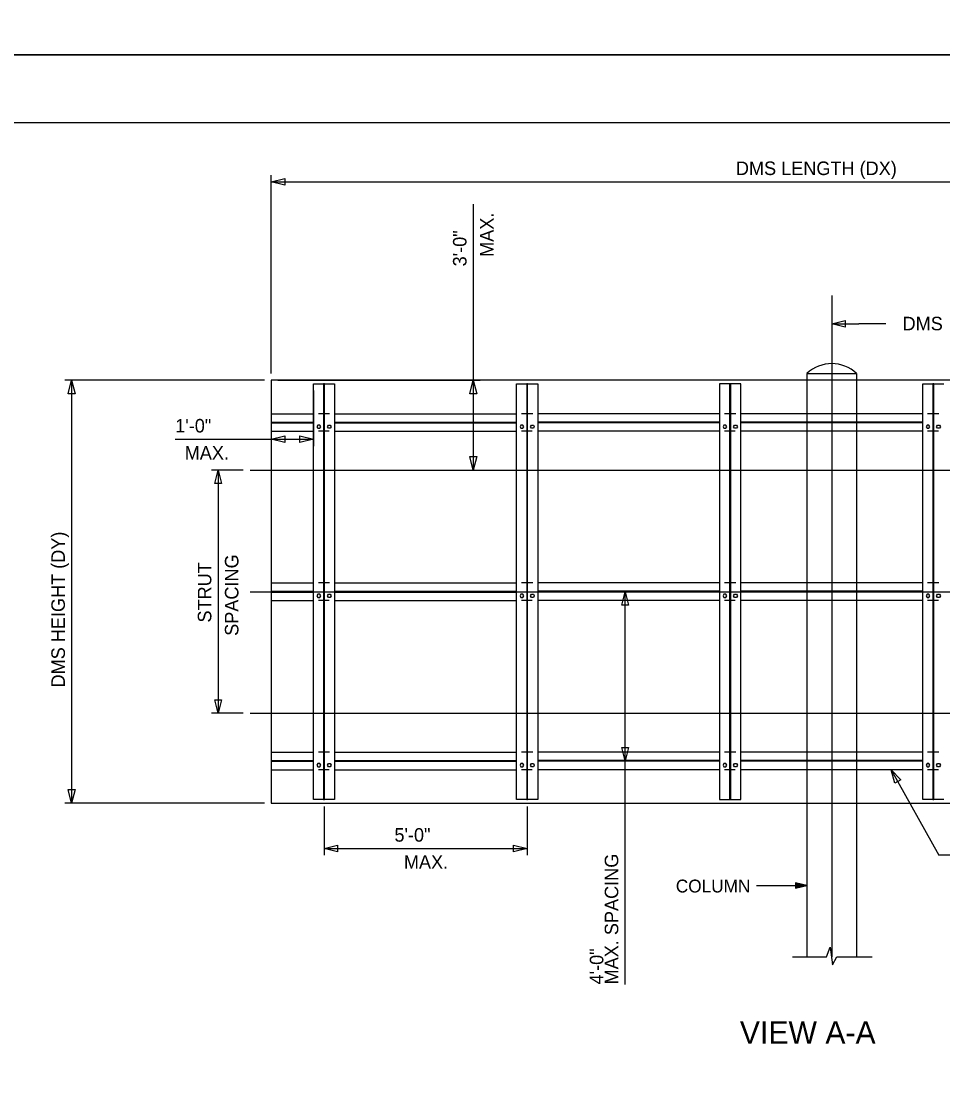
# Model space of a CAD drawing. Extents: x 3829340 to 3831660, y 499389 to 501171.
# Drawn here: x 3830412.4 to 3830616.6, y 499757.1 to 499990.7 of the extents above; entities that cross this region are included whole.
import ezdxf

# ---------------------------------------------------------------- set-up
doc = ezdxf.new("R2010")
doc.units = 0
for name, color, linetype in [('0-ANCHOR', 7, 'Continuous'), ('10', 7, 'Continuous'), ('2', 7, 'Continuous'), ('20', 7, 'Continuous'), ('CNTR', 7, 'Continuous'), ('Default', 7, 'Continuous'), ('DIM TXT', 7, 'Continuous'), ('PLT-BNDY', 7, 'Continuous'), ('sign', 7, 'Continuous'), ('structure', 7, 'Continuous')]:
    doc.layers.add(name, color=color, linetype=linetype)

msp = doc.modelspace()

# ---------------------------------------------------------------- linework, layer by layer
at = {"layer": '0-ANCHOR'}
for p, q in [((3830478.12, 499901.15), (3830477.91, 499900.79)), ((3830477.91, 499900.79), (3830478.12, 499900.43)), ((3830478.53, 499901.15), (3830478.12, 499901.15)), ((3830478.74, 499900.79), (3830478.53, 499901.15)), ((3830478.53, 499900.43), (3830478.74, 499900.79)), ((3830480.24, 499900.79), (3830480.45, 499901.15)), ((3830480.45, 499900.43), (3830480.24, 499900.79)), ((3830480.45, 499901.15), (3830480.87, 499901.15)), ((3830480.87, 499901.15), (3830481.07, 499900.79)), ((3830481.07, 499900.79), (3830480.87, 499900.43)), ((3830523.12, 499901.15), (3830522.91, 499900.79)), ((3830522.91, 499900.79), (3830523.12, 499900.43)), ((3830523.53, 499901.15), (3830523.12, 499901.15)), ((3830523.74, 499900.79), (3830523.53, 499901.15)), ((3830523.53, 499900.43), (3830523.74, 499900.79)), ((3830525.24, 499900.79), (3830525.45, 499901.15)), ((3830525.45, 499900.43), (3830525.24, 499900.79)), ((3830525.45, 499901.15), (3830525.87, 499901.15)), ((3830525.87, 499901.15), (3830526.07, 499900.79)), ((3830526.07, 499900.79), (3830525.87, 499900.43)), ((3830568.11, 499901.15), (3830567.91, 499900.79)), ((3830567.91, 499900.79), (3830568.11, 499900.43)), ((3830568.53, 499901.15), (3830568.11, 499901.15)), ((3830568.74, 499900.79), (3830568.53, 499901.15)), ((3830568.53, 499900.43), (3830568.74, 499900.79)), ((3830570.24, 499900.79), (3830570.45, 499901.15)), ((3830570.45, 499900.43), (3830570.24, 499900.79)), ((3830570.45, 499901.15), (3830570.86, 499901.15)), ((3830570.86, 499901.15), (3830571.07, 499900.79)), ((3830571.07, 499900.79), (3830570.86, 499900.43)), ((3830613.11, 499901.15), (3830612.91, 499900.79)), ((3830612.91, 499900.79), (3830613.11, 499900.43)), ((3830613.53, 499901.15), (3830613.11, 499901.15)), ((3830613.74, 499900.79), (3830613.53, 499901.15)), ((3830613.53, 499900.43), (3830613.74, 499900.79)), ((3830615.24, 499900.79), (3830615.45, 499901.15)), ((3830615.45, 499900.43), (3830615.24, 499900.79)), ((3830615.45, 499901.15), (3830615.86, 499901.15)), ((3830615.86, 499901.15), (3830616.07, 499900.79)), ((3830616.07, 499900.79), (3830615.86, 499900.43)), ((3830478.12, 499900.43), (3830478.53, 499900.43)), ((3830480.87, 499900.43), (3830480.45, 499900.43)), ((3830523.12, 499900.43), (3830523.53, 499900.43)), ((3830525.87, 499900.43), (3830525.45, 499900.43)), ((3830568.11, 499900.43), (3830568.53, 499900.43)), ((3830570.86, 499900.43), (3830570.45, 499900.43)), ((3830613.11, 499900.43), (3830613.53, 499900.43)), ((3830615.86, 499900.43), (3830615.45, 499900.43)), ((3830478.12, 499863.65), (3830477.91, 499863.29)), ((3830478.53, 499863.65), (3830478.12, 499863.65)), ((3830478.74, 499863.29), (3830478.53, 499863.65)), ((3830480.24, 499863.29), (3830480.45, 499863.65)), ((3830480.45, 499863.65), (3830480.87, 499863.65)), ((3830480.87, 499863.65), (3830481.07, 499863.29)), ((3830523.12, 499863.65), (3830522.91, 499863.29)), ((3830523.53, 499863.65), (3830523.12, 499863.65)), ((3830523.74, 499863.29), (3830523.53, 499863.65)), ((3830525.24, 499863.29), (3830525.45, 499863.65)), ((3830525.45, 499863.65), (3830525.87, 499863.65)), ((3830525.87, 499863.65), (3830526.07, 499863.29)), ((3830568.11, 499863.65), (3830567.91, 499863.29)), ((3830568.53, 499863.65), (3830568.11, 499863.65)), ((3830568.74, 499863.29), (3830568.53, 499863.65)), ((3830570.24, 499863.29), (3830570.45, 499863.65)), ((3830570.45, 499863.65), (3830570.86, 499863.65)), ((3830570.86, 499863.65), (3830571.07, 499863.29)), ((3830613.11, 499863.65), (3830612.91, 499863.29)), ((3830613.53, 499863.65), (3830613.11, 499863.65)), ((3830613.74, 499863.29), (3830613.53, 499863.65)), ((3830615.24, 499863.29), (3830615.45, 499863.65)), ((3830615.45, 499863.65), (3830615.86, 499863.65)), ((3830615.86, 499863.65), (3830616.07, 499863.29)), ((3830477.91, 499863.29), (3830478.12, 499862.93)), ((3830478.12, 499862.93), (3830478.53, 499862.93)), ((3830478.53, 499862.93), (3830478.74, 499863.29)), ((3830480.45, 499862.93), (3830480.24, 499863.29)), ((3830480.87, 499862.93), (3830480.45, 499862.93)), ((3830481.07, 499863.29), (3830480.87, 499862.93)), ((3830522.91, 499863.29), (3830523.12, 499862.93)), ((3830523.12, 499862.93), (3830523.53, 499862.93)), ((3830523.53, 499862.93), (3830523.74, 499863.29)), ((3830525.45, 499862.93), (3830525.24, 499863.29)), ((3830525.87, 499862.93), (3830525.45, 499862.93)), ((3830526.07, 499863.29), (3830525.87, 499862.93)), ((3830567.91, 499863.29), (3830568.11, 499862.93)), ((3830568.11, 499862.93), (3830568.53, 499862.93)), ((3830568.53, 499862.93), (3830568.74, 499863.29)), ((3830570.45, 499862.93), (3830570.24, 499863.29)), ((3830570.86, 499862.93), (3830570.45, 499862.93)), ((3830571.07, 499863.29), (3830570.86, 499862.93)), ((3830612.91, 499863.29), (3830613.11, 499862.93)), ((3830613.11, 499862.93), (3830613.53, 499862.93)), ((3830613.53, 499862.93), (3830613.74, 499863.29)), ((3830615.45, 499862.93), (3830615.24, 499863.29)), ((3830615.86, 499862.93), (3830615.45, 499862.93)), ((3830616.07, 499863.29), (3830615.86, 499862.93)), ((3830478.12, 499826.15), (3830477.91, 499825.79)), ((3830478.53, 499826.15), (3830478.12, 499826.15)), ((3830478.74, 499825.79), (3830478.53, 499826.15)), ((3830480.24, 499825.79), (3830480.45, 499826.15)), ((3830480.45, 499826.15), (3830480.87, 499826.15)), ((3830480.87, 499826.15), (3830481.07, 499825.79)), ((3830523.12, 499826.15), (3830522.91, 499825.79)), ((3830523.53, 499826.15), (3830523.12, 499826.15)), ((3830523.74, 499825.79), (3830523.53, 499826.15)), ((3830525.24, 499825.79), (3830525.45, 499826.15)), ((3830525.45, 499826.15), (3830525.87, 499826.15)), ((3830525.87, 499826.15), (3830526.07, 499825.79)), ((3830568.11, 499826.15), (3830567.91, 499825.79)), ((3830568.53, 499826.15), (3830568.11, 499826.15)), ((3830568.74, 499825.79), (3830568.53, 499826.15)), ((3830570.24, 499825.79), (3830570.45, 499826.15)), ((3830570.45, 499826.15), (3830570.86, 499826.15)), ((3830570.86, 499826.15), (3830571.07, 499825.79)), ((3830613.11, 499826.15), (3830612.91, 499825.79)), ((3830613.53, 499826.15), (3830613.11, 499826.15)), ((3830613.74, 499825.79), (3830613.53, 499826.15)), ((3830615.24, 499825.79), (3830615.45, 499826.15)), ((3830615.45, 499826.15), (3830615.86, 499826.15)), ((3830615.86, 499826.15), (3830616.07, 499825.79)), ((3830477.91, 499825.79), (3830478.12, 499825.43)), ((3830478.12, 499825.43), (3830478.53, 499825.43)), ((3830478.53, 499825.43), (3830478.74, 499825.79)), ((3830480.45, 499825.43), (3830480.24, 499825.79)), ((3830480.87, 499825.43), (3830480.45, 499825.43)), ((3830481.07, 499825.79), (3830480.87, 499825.43)), ((3830522.91, 499825.79), (3830523.12, 499825.43)), ((3830523.12, 499825.43), (3830523.53, 499825.43)), ((3830523.53, 499825.43), (3830523.74, 499825.79)), ((3830525.45, 499825.43), (3830525.24, 499825.79)), ((3830525.87, 499825.43), (3830525.45, 499825.43)), ((3830526.07, 499825.79), (3830525.87, 499825.43)), ((3830567.91, 499825.79), (3830568.11, 499825.43)), ((3830568.11, 499825.43), (3830568.53, 499825.43)), ((3830568.53, 499825.43), (3830568.74, 499825.79)), ((3830570.45, 499825.43), (3830570.24, 499825.79)), ((3830570.86, 499825.43), (3830570.45, 499825.43)), ((3830571.07, 499825.79), (3830570.86, 499825.43)), ((3830612.91, 499825.79), (3830613.11, 499825.43)), ((3830613.11, 499825.43), (3830613.53, 499825.43)), ((3830613.53, 499825.43), (3830613.74, 499825.79)), ((3830615.45, 499825.43), (3830615.24, 499825.79)), ((3830615.86, 499825.43), (3830615.45, 499825.43)), ((3830616.07, 499825.79), (3830615.86, 499825.43))]:
    msp.add_line(p, q, dxfattribs=at)
at = {"layer": '10'}
for p, q in [((3830575.31, 499799.1), (3830586.47, 499799.1)), ((3830586.47, 499799.1), (3830583.98, 499799.72)), ((3830583.98, 499799.72), (3830583.98, 499798.48)), ((3830583.98, 499798.48), (3830586.47, 499799.1)), ((3830585.86, 499799.1), (3830584.13, 499799.53)), ((3830584.13, 499799.53), (3830584.13, 499798.66)), ((3830584.13, 499798.66), (3830585.86, 499799.1)), ((3830585.25, 499799.1), (3830584.27, 499799.34)), ((3830584.27, 499799.34), (3830584.27, 499798.85)), ((3830584.27, 499798.85), (3830585.25, 499799.1)), ((3830584.33, 499799.02), (3830584.65, 499799.1)), ((3830584.65, 499799.1), (3830584.35, 499799.17))]:
    msp.add_line(p, q, dxfattribs=at)
at = {"layer": '2'}
msp.add_line((3830220.96, 499968.19), (3831006.96, 499968.19), dxfattribs=at)
at = {"layer": '20'}
for p, q in [((3830586.47, 499912.57), (3830597.51, 499912.57)), ((3830586.47, 499912.57), (3830586.47, 499911.09)), ((3830597.51, 499912.57), (3830597.51, 499911.09)), ((3830586.47, 499911.09), (3830586.47, 499817.35)), ((3830597.51, 499911.09), (3830597.51, 499817.35)), ((3830586.47, 499817.35), (3830586.47, 499783.31)), ((3830597.51, 499817.35), (3830597.51, 499783.31)), ((3830590.81, 499783.31), (3830591.64, 499785.42)), ((3830591.64, 499785.42), (3830592.18, 499781.54)), ((3830583.27, 499783.31), (3830590.81, 499783.31)), ((3830592.18, 499781.54), (3830593.12, 499783.31)), ((3830593.12, 499783.31), (3830600.93, 499783.31))]:
    msp.add_line(p, q, dxfattribs=at)
msp.add_arc((3830591.99, 499906.77), 8, 46.3972, 133.6028, dxfattribs=at)
at = {"layer": 'CNTR'}
for p, q in [((3830591.99, 499929.84), (3830591.99, 499783.31)), ((3830463.09, 499891.17), (3830749.83, 499891.17)), ((3830463.09, 499864.22), (3830763.65, 499864.22)), ((3830463.09, 499837.27), (3830749.59, 499837.27))]:
    msp.add_line(p, q, dxfattribs=at)
at = {"layer": 'DIM TXT'}
for p, q in [((3830467.77, 499912.59), (3830467.77, 499956.56)), ((3830467.77, 499955.06), (3830716.2, 499955.06)), ((3830512.56, 499950.14), (3830512.56, 499911.09)), ((3830591.99, 499923.59), (3830597.99, 499923.59)), ((3830603.99, 499923.59), (3830597.99, 499923.59)), ((3830466.27, 499911.09), (3830422.06, 499911.09)), ((3830423.56, 499911.09), (3830423.56, 499817.35)), ((3830469.27, 499911.09), (3830514.06, 499911.09)), ((3830512.56, 499911.09), (3830512.56, 499891.17)), ((3830477.15, 499908.81), (3830477.15, 499896.5)), ((3830467.78, 499902.17), (3830467.78, 499896.5)), ((3830446.51, 499898), (3830467.78, 499898)), ((3830467.78, 499898), (3830477.15, 499898)), ((3830461.59, 499891.17), (3830454.52, 499891.17)), ((3830456.02, 499891.17), (3830456.02, 499837.27)), ((3830469.27, 499891.17), (3830514.06, 499891.17)), ((3830565.65, 499864.22), (3830544.69, 499864.22)), ((3830546.19, 499826.72), (3830546.19, 499864.22)), ((3830461.59, 499837.27), (3830454.52, 499837.27)), ((3830565.65, 499826.72), (3830544.69, 499826.72)), ((3830546.19, 499777.17), (3830546.19, 499826.72)), ((3830605.17, 499824.77), (3830615.71, 499805.83)), ((3830466.27, 499817.35), (3830422.06, 499817.35)), ((3830479.49, 499816.63), (3830479.49, 499805.81)), ((3830524.49, 499816.63), (3830524.49, 499805.81)), ((3830479.49, 499807.31), (3830524.49, 499807.31)), ((3830621.71, 499805.83), (3830615.71, 499805.83))]:
    msp.add_line(p, q, dxfattribs=at)
for points in [[(3830470.77, 499954.31), (3830467.77, 499955.06), (3830470.77, 499955.81)], [(3830594.99, 499922.84), (3830591.99, 499923.59), (3830594.99, 499924.34)], [(3830422.81, 499908.09), (3830423.56, 499911.09), (3830424.31, 499908.09)], [(3830511.81, 499908.09), (3830512.56, 499911.09), (3830513.31, 499908.09)], [(3830470.78, 499897.25), (3830467.78, 499898), (3830470.78, 499898.75)], [(3830474.15, 499898.75), (3830477.15, 499898), (3830474.15, 499897.25)], [(3830513.31, 499894.17), (3830512.56, 499891.17), (3830511.81, 499894.17)], [(3830455.27, 499888.17), (3830456.02, 499891.17), (3830456.77, 499888.17)], [(3830545.44, 499861.22), (3830546.19, 499864.22), (3830546.94, 499861.22)], [(3830456.77, 499840.27), (3830456.02, 499837.27), (3830455.27, 499840.27)], [(3830546.94, 499829.72), (3830546.19, 499826.72), (3830545.44, 499829.72)], [(3830605.98, 499821.78), (3830605.17, 499824.77), (3830607.29, 499822.51)], [(3830424.31, 499820.35), (3830423.56, 499817.35), (3830422.81, 499820.35)], [(3830482.49, 499806.56), (3830479.49, 499807.31), (3830482.49, 499808.06)], [(3830521.49, 499808.06), (3830524.49, 499807.31), (3830521.49, 499806.56)]]:
    msp.add_lwpolyline(points, close=True, dxfattribs=at)
at = {"layer": 'PLT-BNDY'}
for points in [[(3830180.96, 500577.19), (3831021.96, 500577.19), (3831021.96, 499983.19), (3830180.96, 499983.19)], [(3830180.96, 499983.19), (3831021.96, 499983.19), (3831021.96, 499389.19), (3830180.96, 499389.19)]]:
    msp.add_lwpolyline(points, close=True, dxfattribs=at)
at = {"layer": 'sign'}
for p, q in [((3830716.2, 499911.09), (3830467.77, 499911.09)), ((3830467.77, 499911.09), (3830467.77, 499817.35)), ((3830467.78, 499903.67), (3830467.78, 499899.77)), ((3830467.78, 499903.67), (3830477.15, 499903.67)), ((3830480.72, 499903.67), (3830478.23, 499903.67)), ((3830481.83, 499903.67), (3830522.15, 499903.67)), ((3830525.72, 499903.67), (3830523.23, 499903.67)), ((3830567.15, 499903.67), (3830526.83, 499903.67)), ((3830570.72, 499903.67), (3830568.23, 499903.67)), ((3830612.15, 499903.67), (3830571.83, 499903.67)), ((3830615.72, 499903.67), (3830613.23, 499903.67)), ((3830467.78, 499901.82), (3830477.15, 499901.82)), ((3830467.78, 499901.62), (3830477.15, 499901.62)), ((3830481.83, 499901.82), (3830522.15, 499901.82)), ((3830481.83, 499901.62), (3830522.15, 499901.62)), ((3830567.15, 499901.82), (3830526.83, 499901.82)), ((3830567.15, 499901.62), (3830526.83, 499901.62)), ((3830612.15, 499901.82), (3830571.83, 499901.82)), ((3830612.15, 499901.62), (3830571.83, 499901.62)), ((3830467.78, 499899.77), (3830477.15, 499899.77)), ((3830480.61, 499899.77), (3830478.23, 499899.77)), ((3830481.83, 499899.77), (3830522.15, 499899.77)), ((3830525.61, 499899.77), (3830523.23, 499899.77)), ((3830567.15, 499899.77), (3830526.83, 499899.77)), ((3830570.61, 499899.77), (3830568.23, 499899.77)), ((3830612.15, 499899.77), (3830571.83, 499899.77)), ((3830615.61, 499899.77), (3830613.23, 499899.77)), ((3830467.78, 499866.17), (3830467.78, 499862.27)), ((3830467.78, 499866.17), (3830477.15, 499866.17)), ((3830480.72, 499866.17), (3830478.23, 499866.17)), ((3830481.83, 499866.17), (3830522.15, 499866.17)), ((3830525.72, 499866.17), (3830523.23, 499866.17)), ((3830567.15, 499866.17), (3830526.83, 499866.17)), ((3830570.72, 499866.17), (3830568.23, 499866.17)), ((3830612.15, 499866.17), (3830571.83, 499866.17)), ((3830615.72, 499866.17), (3830613.23, 499866.17)), ((3830467.78, 499864.32), (3830477.15, 499864.32)), ((3830467.78, 499864.12), (3830477.15, 499864.12)), ((3830481.83, 499864.32), (3830522.15, 499864.32)), ((3830481.83, 499864.12), (3830522.15, 499864.12)), ((3830567.15, 499864.32), (3830526.83, 499864.32)), ((3830567.15, 499864.12), (3830526.83, 499864.12)), ((3830612.15, 499864.32), (3830571.83, 499864.32)), ((3830612.15, 499864.12), (3830571.83, 499864.12)), ((3830467.78, 499862.27), (3830477.15, 499862.27)), ((3830480.61, 499862.27), (3830478.23, 499862.27)), ((3830481.83, 499862.27), (3830522.15, 499862.27)), ((3830525.61, 499862.27), (3830523.23, 499862.27)), ((3830567.15, 499862.27), (3830526.83, 499862.27)), ((3830570.61, 499862.27), (3830568.23, 499862.27)), ((3830612.15, 499862.27), (3830571.83, 499862.27)), ((3830615.61, 499862.27), (3830613.23, 499862.27)), ((3830467.78, 499828.67), (3830467.78, 499824.77)), ((3830467.78, 499828.67), (3830477.15, 499828.67)), ((3830480.72, 499828.67), (3830478.23, 499828.67)), ((3830481.83, 499828.67), (3830522.15, 499828.67)), ((3830525.72, 499828.67), (3830523.23, 499828.67)), ((3830567.15, 499828.67), (3830526.83, 499828.67)), ((3830570.72, 499828.67), (3830568.23, 499828.67)), ((3830612.15, 499828.67), (3830571.83, 499828.67)), ((3830615.72, 499828.67), (3830613.23, 499828.67)), ((3830467.78, 499826.82), (3830477.15, 499826.82)), ((3830467.78, 499826.62), (3830477.15, 499826.62)), ((3830481.83, 499826.82), (3830522.15, 499826.82)), ((3830481.83, 499826.62), (3830522.15, 499826.62)), ((3830567.15, 499826.82), (3830526.83, 499826.82)), ((3830567.15, 499826.62), (3830526.83, 499826.62)), ((3830612.15, 499826.82), (3830571.83, 499826.82)), ((3830612.15, 499826.62), (3830571.83, 499826.62)), ((3830467.78, 499824.77), (3830477.15, 499824.77)), ((3830480.61, 499824.77), (3830478.23, 499824.77)), ((3830481.83, 499824.77), (3830522.15, 499824.77)), ((3830525.61, 499824.77), (3830523.23, 499824.77)), ((3830567.15, 499824.77), (3830526.83, 499824.77)), ((3830570.61, 499824.77), (3830568.23, 499824.77)), ((3830612.15, 499824.77), (3830571.83, 499824.77)), ((3830615.61, 499824.77), (3830613.23, 499824.77)), ((3830467.77, 499817.35), (3830716.2, 499817.35))]:
    msp.add_line(p, q, dxfattribs=at)
at = {"layer": 'structure'}
for p, q in [((3830477.15, 499910.31), (3830481.83, 499910.31)), ((3830477.15, 499818.13), (3830477.15, 499910.31)), ((3830479.58, 499910.31), (3830479.4, 499910.31)), ((3830479.4, 499910.31), (3830479.4, 499818.13)), ((3830479.58, 499818.13), (3830479.58, 499910.31)), ((3830481.83, 499910.31), (3830481.83, 499818.13)), ((3830522.15, 499910.31), (3830526.83, 499910.31)), ((3830522.15, 499818.13), (3830522.15, 499910.31)), ((3830524.58, 499910.31), (3830524.4, 499910.31)), ((3830524.4, 499910.31), (3830524.4, 499818.13)), ((3830524.58, 499818.13), (3830524.58, 499910.31)), ((3830526.83, 499910.31), (3830526.83, 499818.13)), ((3830571.83, 499910.31), (3830567.15, 499910.31)), ((3830567.15, 499910.31), (3830567.15, 499818.13)), ((3830569.4, 499910.31), (3830569.58, 499910.31)), ((3830569.4, 499818.13), (3830569.4, 499910.31)), ((3830569.58, 499910.31), (3830569.58, 499818.13)), ((3830571.83, 499818.13), (3830571.83, 499910.31)), ((3830612.15, 499910.31), (3830616.83, 499910.31)), ((3830612.15, 499818.13), (3830612.15, 499910.31)), ((3830614.58, 499910.31), (3830614.4, 499910.31)), ((3830614.4, 499910.31), (3830614.4, 499818.13)), ((3830614.58, 499818.13), (3830614.58, 499910.31)), ((3830481.83, 499818.13), (3830477.15, 499818.13)), ((3830479.4, 499818.13), (3830479.58, 499818.13)), ((3830526.83, 499818.13), (3830522.15, 499818.13)), ((3830524.4, 499818.13), (3830524.58, 499818.13)), ((3830567.15, 499818.13), (3830571.83, 499818.13)), ((3830569.58, 499818.13), (3830569.4, 499818.13)), ((3830616.83, 499818.13), (3830612.15, 499818.13)), ((3830614.4, 499818.13), (3830614.58, 499818.13))]:
    msp.add_line(p, q, dxfattribs=at)

# ---------------------------------------------------------------- texts
at = {"layer": '10'}
msp.add_text('COLUMN', height=2.852, dxfattribs=at).set_placement((3830557.44, 499797.55))
at = {"layer": 'Default'}
msp.add_text('VIEW A-A', height=5, dxfattribs=at).set_placement((3830571.63, 499764.02))
at = {"layer": 'DIM TXT'}
for s, height, p in [('DMS LENGTH (DX)', 2.9999, (3830570.75, 499956.56)), ('  DMS', 3, (3830605.46, 499922.15)), ('1\'-0"', 3, (3830446.51, 499899.5)), ('MAX.', 3, (3830448.61, 499893.5)), ('5\'-0"', 3, (3830495.08, 499808.81)), ('MAX.', 3, (3830497.18, 499802.81))]:
    msp.add_text(s, height=height, dxfattribs=at).set_placement(p)
for s, height, p in [('MAX.', 3, (3830517.06, 499938.42)), ('3\'-0"', 3, (3830511.06, 499936.32)), ('DMS HEIGHT (DY)', 2.9999, (3830422.06, 499842.99)), ('STRUT', 3, (3830454.52, 499857.38)), ('SPACING', 3, (3830460.52, 499854.43)), ('MAX. SPACING', 2.9999, (3830544.69, 499777.17)), ('4\'-0"', 3, (3830541.38, 499777.17))]:
    msp.add_text(s, height=height, rotation=90, dxfattribs=at).set_placement(p)

doc.saveas('drawing.dxf')
